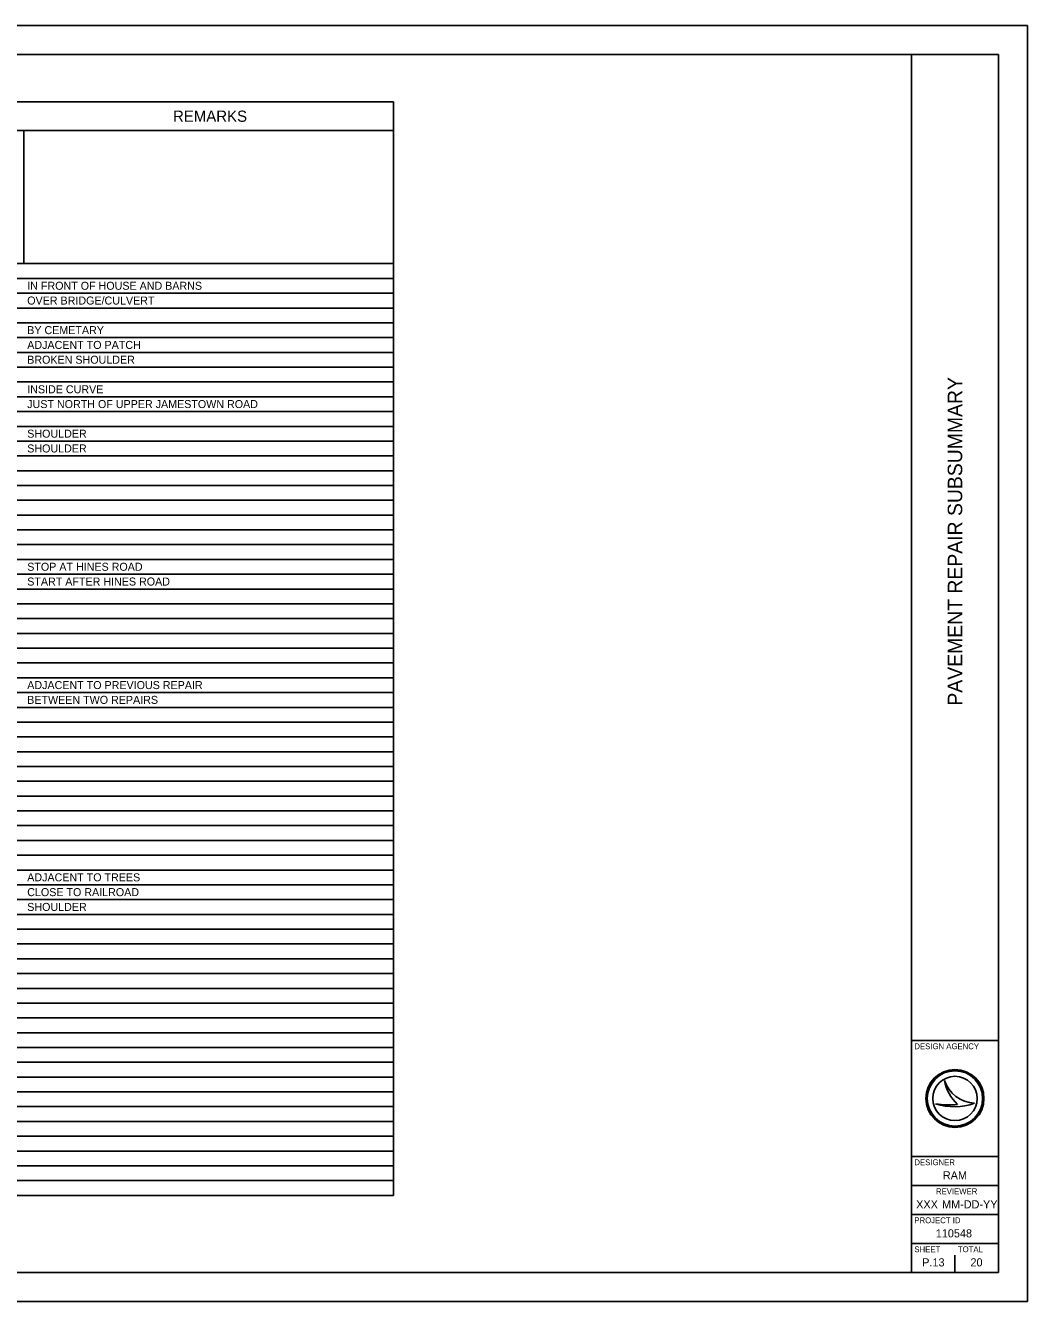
# Model space of a CAD drawing. Extents: x 0 to 34, y 0 to 22.
# Drawn here: x 16.72 to 34, y 0 to 22 of the extents above; entities that cross this region are included whole.
import ezdxf

# ---------------------------------------------------------------- set-up
doc = ezdxf.new("R2010")
doc.units = 0
for name, color, linetype in [('SH_Border', 7, 'Continuous'), ('SH_Cut_Line', 7, 'Continuous'), ('SH_Data', 7, 'Continuous'), ('SH_Text', 7, 'Continuous')]:
    doc.layers.add(name, color=color, linetype=linetype)

msp = doc.modelspace()

# ---------------------------------------------------------------- linework, layer by layer
at = {"layer": 'SH_Border'}
for p, q in [((32, 0.5), (32, 21.5)), ((32, 4.5), (33.5, 4.5)), ((32, 2.5), (33.5, 2.5)), ((32, 2), (33.5, 2)), ((32, 1.5), (33.5, 1.5)), ((32, 1), (33.5, 1))]:
    msp.add_line(p, q, dxfattribs=at)
msp.add_lwpolyline([(1.5, 21.5), (33.5, 21.5), (33.5, 0.5), (1.5, 0.5)], close=True, dxfattribs=at)
at = {"layer": 'SH_Cut_Line'}
msp.add_lwpolyline([(0, 0), (34, 0), (34, 22), (0, 22)], close=True, dxfattribs=at)
at = {"layer": 'SH_Data'}
for p, q in [((32.567, 3.81), (32.567, 3.81)), ((32.417, 3.41), (32.417, 3.41)), ((32.75, 3.5), (32.75, 3.5)), ((33.087, 3.419), (33.087, 3.419)), ((32.375, 0.675), (32.375, 0.675)), ((32.75, 0.5), (32.75, 0.8))]:
    msp.add_line(p, q, dxfattribs=at)
for radius in [0.5, 0.477, 0.477, 0.382]:
    msp.add_circle((32.75, 3.5), radius, dxfattribs=at)
for centre, radius, start, end in [((33.116, 3.998), 0.58, 198.9257, 198.9319), ((33.347, 3.97), 0.796, 191.6379, 191.6421), ((33.116, 3.998), 0.58, 198.9319, 267.1657), ((33.347, 3.97), 0.796, 191.6421, 226.0947), ((32.739, 4.37), 1.013, 251.4576, 290.0832), ((32.648, 4.654), 1.266, 259.4964, 259.4995), ((32.739, 4.37), 1.013, 251.4527, 251.4576), ((32.648, 4.654), 1.266, 259.4995, 276.6672)]:
    msp.add_arc(centre, radius, start, end, dxfattribs=at)
at = {"layer": 'SH_Text'}
for p, q in [((9.014, 20.684), (23.069, 20.684)), ((23.069, 20.684), (23.069, 1.829)), ((9.014, 20.189), (23.069, 20.189)), ((9.014, 17.894), (23.069, 17.894)), ((9.014, 17.639), (23.069, 17.639)), ((9.014, 17.384), (23.069, 17.384)), ((9.014, 17.129), (23.069, 17.129)), ((9.014, 16.874), (23.069, 16.874)), ((9.014, 16.619), (23.069, 16.619)), ((9.014, 16.364), (23.069, 16.364)), ((9.014, 16.109), (23.069, 16.109)), ((9.014, 15.854), (23.069, 15.854)), ((9.014, 15.599), (23.069, 15.599)), ((9.014, 15.344), (23.069, 15.344)), ((9.014, 15.089), (23.069, 15.089)), ((9.014, 14.834), (23.069, 14.834)), ((9.014, 14.579), (23.069, 14.579)), ((9.014, 14.324), (23.069, 14.324)), ((9.014, 14.069), (23.069, 14.069)), ((9.014, 13.814), (23.069, 13.814)), ((9.014, 13.559), (23.069, 13.559)), ((9.014, 13.304), (23.069, 13.304)), ((9.014, 13.049), (23.069, 13.049)), ((9.014, 12.794), (23.069, 12.794)), ((9.014, 12.539), (23.069, 12.539)), ((9.014, 12.284), (23.069, 12.284)), ((9.014, 12.029), (23.069, 12.029)), ((9.014, 11.774), (23.069, 11.774)), ((9.014, 11.519), (23.069, 11.519)), ((9.014, 11.264), (23.069, 11.264)), ((9.014, 11.009), (23.069, 11.009)), ((9.014, 10.754), (23.069, 10.754)), ((9.014, 10.499), (23.069, 10.499)), ((9.014, 10.244), (23.069, 10.244)), ((9.014, 9.989), (23.069, 9.989)), ((9.014, 9.734), (23.069, 9.734)), ((9.014, 9.479), (23.069, 9.479)), ((9.014, 9.224), (23.069, 9.224)), ((9.014, 8.969), (23.069, 8.969)), ((9.014, 8.714), (23.069, 8.714)), ((9.014, 8.459), (23.069, 8.459)), ((9.014, 8.204), (23.069, 8.204)), ((9.014, 7.949), (23.069, 7.949)), ((9.014, 7.694), (23.069, 7.694)), ((9.014, 7.439), (23.069, 7.439)), ((9.014, 7.184), (23.069, 7.184)), ((9.014, 6.929), (23.069, 6.929)), ((9.014, 6.674), (23.069, 6.674)), ((9.014, 6.419), (23.069, 6.419)), ((9.014, 6.164), (23.069, 6.164)), ((9.014, 5.909), (23.069, 5.909)), ((9.014, 5.654), (23.069, 5.654)), ((9.014, 5.399), (23.069, 5.399)), ((9.014, 5.144), (23.069, 5.144)), ((9.014, 4.889), (23.069, 4.889)), ((9.014, 4.634), (23.069, 4.634)), ((9.014, 4.379), (23.069, 4.379)), ((9.014, 4.124), (23.069, 4.124)), ((9.014, 3.869), (23.069, 3.869)), ((9.014, 3.614), (23.069, 3.614)), ((9.014, 3.359), (23.069, 3.359)), ((9.014, 3.104), (23.069, 3.104)), ((9.014, 2.849), (23.069, 2.849)), ((9.014, 2.594), (23.069, 2.594)), ((9.014, 2.339), (23.069, 2.339)), ((9.014, 2.084), (23.069, 2.084)), ((9.014, 1.829), (23.069, 1.829))]:
    msp.add_line(p, q, dxfattribs=at)
msp.add_lwpolyline([(16.694, 20.189), (23.069, 20.189), (23.069, 17.894), (16.694, 17.894)], close=True, dxfattribs=at)

# ---------------------------------------------------------------- texts
at = {"layer": 'SH_Data'}
msp.add_text('PAVEMENT REPAIR SUBSUMMARY', height=0.25, rotation=90, dxfattribs=at).set_placement((32.875, 10.273))
for s, height, p in [('DESIGN AGENCY', 0.1, (32.05, 4.35)), ('DESIGNER', 0.1, (32.05, 2.35)), ('RAM', 0.14, (32.541, 2.105)), ('REVIEWER', 0.1, (32.422, 1.85)), ('XXX', 0.14, (32.081, 1.605)), ('MM-DD-YY', 0.14, (32.527, 1.605)), ('PROJECT ID', 0.1, (32.05, 1.35)), ('110548', 0.14, (32.419, 1.105)), ('SHEET', 0.1, (32.05, 0.85)), ('TOTAL', 0.1, (32.8, 0.85)), ('P.13', 0.14, (32.185, 0.605)), ('20', 0.14, (33.017, 0.605))]:
    msp.add_text(s, height=height, dxfattribs=at).set_placement(p)
at = {"layer": 'SH_Text'}
for s, height, p in [('REMARKS', 0.1932, (19.267, 20.34)), ('IN FRONT OF HOUSE AND BARNS', 0.138, (16.754, 17.444)), ('OVER BRIDGE/CULVERT', 0.138, (16.754, 17.189)), ('BY CEMETARY', 0.138, (16.754, 16.679)), ('ADJACENT TO PATCH', 0.138, (16.754, 16.424)), ('BROKEN SHOULDER', 0.138, (16.754, 16.169)), ('INSIDE CURVE', 0.138, (16.754, 15.659)), ('JUST NORTH OF UPPER JAMESTOWN ROAD', 0.138, (16.754, 15.404)), ('SHOULDER', 0.138, (16.754, 14.894)), ('SHOULDER', 0.138, (16.754, 14.639)), ('STOP AT HINES ROAD', 0.138, (16.754, 12.599)), ('START AFTER HINES ROAD', 0.138, (16.754, 12.344)), ('ADJACENT TO PREVIOUS REPAIR', 0.138, (16.754, 10.559)), ('BETWEEN TWO REPAIRS', 0.138, (16.754, 10.304)), ('ADJACENT TO TREES', 0.138, (16.754, 7.244)), ('CLOSE TO RAILROAD', 0.138, (16.754, 6.989)), ('SHOULDER', 0.138, (16.754, 6.734))]:
    msp.add_text(s, height=height, dxfattribs=at).set_placement(p)

doc.saveas('drawing.dxf')
